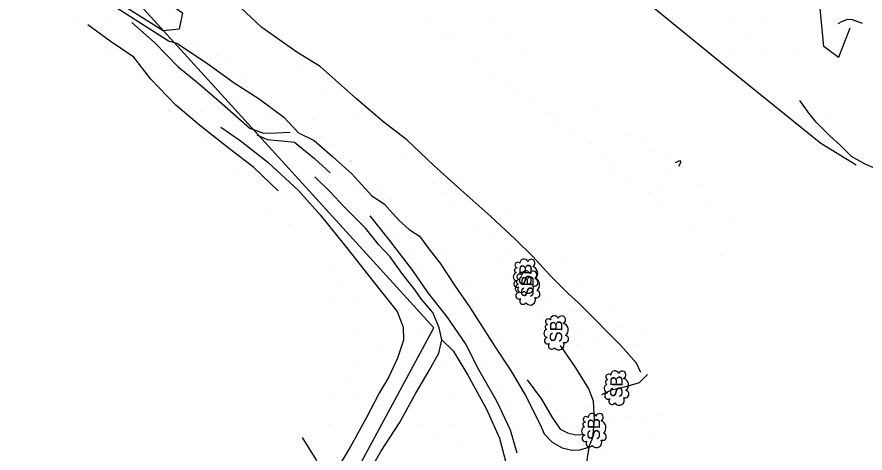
# Model space of a CAD drawing. Extents: x 19528164 to 19545171, y 7585743 to 7602745.
# Drawn here: x 19530420 to 19530964, y 7590962 to 7591242 of the extents above; entities that cross this region are included whole.
import ezdxf

# ---------------------------------------------------------------- set-up
doc = ezdxf.new("R2010")
doc.units = 0
for name, color, linetype in [('Default', 7, 'Continuous'), ('PhoBreakLine', 7, 'Continuous'), ('PhoCulvert', 7, 'Continuous'), ('PhoISAEPoints', 7, 'Continuous'), ('PhoSurveyLimits', 7, 'Continuous'), ('PhoVegetation', 7, 'Continuous'), ('SurNaturalCells', 7, 'Continuous')]:
    doc.layers.add(name, color=color, linetype=linetype)

# ---------------------------------------------------------------- blocks, each defined once
blk = doc.blocks.new('SHRUB')
at = {"layer": 'Default'}
for centre, radius, start, end in [((-5.57, 5.14), 2.08, 10.5948, 214.3611), ((-0.81, 4.83), 2.81, 22.6036, 165.7836), ((3.27, 5.33), 1.59, 0.4605, 158.7839), ((6.61, 4.92), 1.8, 311.3936, 166.4114), ((-8.06, -2.12), 3.34, 125.8289, 299.2848), ((-8.82, 2.41), 2.18, 45.3455, 236.8073), ((8, 0.98), 2.6, 290.9039, 94.3687), ((-4.25, -5.95), 2.36, 157.0258, 349.7602), ((1.54, -3.45), 4.54, 220.0183, 343.6977), ((8.09, -3.71), 2.42, 204.8294, 69.8871)]:
    blk.add_arc(centre, radius, start, end, dxfattribs=at)
blk.add_text('SB', height=7.998, dxfattribs=at).set_placement((-6.62, -4.17))

msp = doc.modelspace()

# ---------------------------------------------------------------- linework, layer by layer
at = {"layer": 'PhoBreakLine'}
for points in [[(19530958.62, 7591146.45), (19530935.96, 7591160.42), (19530877.06, 7591207.86), (19530821.43, 7591253.41), (19530757.71, 7591304.42), (19530691.34, 7591359.14), (19530627.59, 7591412.48), (19530548.14, 7591471.69), (19530520.95, 7591498.59), (19530518.59, 7591512.8), (19530520.19, 7591521.96)], [(19530614.51, 7591209.79), (19530599.48, 7591218.98), (19530577.11, 7591234.92), (19530553.06, 7591257.5), (19530528.71, 7591275.49), (19530499.96, 7591300.16), (19530470.89, 7591323.45), (19530447.93, 7591343.39), (19530419.35, 7591366.44), (19530395.66, 7591387.51), (19530367.82, 7591410.31), (19530342.4, 7591430.71), (19530313.46, 7591452.79), (19530284.41, 7591476.2)], [(19530428.45, 7591286.93), (19530449.8, 7591271.1), (19530480.16, 7591249.8), (19530508.07, 7591232.05), (19530517.08, 7591226.35), (19530522.95, 7591224.48)], [(19530954.64, 7591234.5), (19530947.42, 7591215.59), (19530938.04, 7591222.58), (19530935.37, 7591249.47)], [(19530587.58, 7591130.01), (19530571.82, 7591144.85), (19530556.19, 7591157), (19530537.03, 7591172.18), (19530521.78, 7591184.9), (19530505.73, 7591201.61), (19530494.85, 7591215.79), (19530479.6, 7591225.96), (19530465.37, 7591236.52)], [(19530493.62, 7591238.04), (19530508.36, 7591225.08), (19530523.21, 7591209.53), (19530523.21, 7591209.53), (19530535.7, 7591199.6), (19530549.69, 7591187.59), (19530569.42, 7591170.12), (19530578.12, 7591166.98), (19530586.47, 7591167.23), (19530595.18, 7591167.66)], [(19530962.83, 7591237.33), (19530956.4, 7591239.66), (19530952.87, 7591239.91), (19530949.24, 7591238.43), (19530947.04, 7591237.25)], [(19530522.95, 7591224.48), (19530542.26, 7591211.58), (19530559.32, 7591199.29), (19530575.37, 7591189.01), (19530591.17, 7591177.27), (19530600.49, 7591167.2), (19530610.67, 7591162.19), (19530622.41, 7591152.02), (19530634.73, 7591140.77), (19530647.57, 7591126.78), (19530655.54, 7591121.52), (19530664.78, 7591111.27), (19530671.64, 7591105.1), (19530678.37, 7591100.91), (19530684.18, 7591092.82), (19530691.3, 7591083.67), (19530701.09, 7591068.82), (19530710.45, 7591055.49), (19530718.72, 7591042.45), (19530726.19, 7591030.55), (19530736.78, 7591014.88), (19530746.16, 7590998.94), (19530755.75, 7590979.88), (19530758.45, 7590973.86), (19530763.54, 7590968.49), (19530769.92, 7590965), (19530776.06, 7590963.46), (19530781.29, 7590963.6), (19530786.93, 7590965.34), (19530789.5, 7590971.51), (19530790.6, 7590982.83), (19530790.09, 7590994.9), (19530787.04, 7591002.86), (19530778.78, 7591016.25), (19530768.81, 7591030.75)], [(19530820.43, 7591013.29), (19530817.59, 7591019.23), (19530807.48, 7591030.66), (19530799.16, 7591038.92), (19530790.14, 7591048.17), (19530780.36, 7591058.09), (19530773.66, 7591064), (19530762.34, 7591075.4), (19530751.1, 7591087.77), (19530739.81, 7591099.03), (19530724.17, 7591113.56), (19530704.88, 7591130.56), (19530687.38, 7591146.23), (19530670.04, 7591162.69), (19530654.41, 7591174.66), (19530637.88, 7591188.93), (19530614.51, 7591209.79)], [(19530971.48, 7591144.19), (19530964.47, 7591147.13), (19530955.72, 7591152.08), (19530948.4, 7591159.18), (19530941.84, 7591165.23), (19530932.99, 7591174.06), (19530928.61, 7591179.51), (19530922.57, 7591187.9)], [(19530550.69, 7591170.8), (19530563.11, 7591162.21), (19530580.92, 7591148.29), (19530600.48, 7591130.16), (19530614.58, 7591114.45), (19530632.27, 7591092.51), (19530647.29, 7591073.38), (19530663.97, 7591052.42), (19530667.84, 7591042.43), (19530667.95, 7591034.18), (19530664.24, 7591022.5), (19530658.51, 7591010.63), (19530652.31, 7591000.06), (19530644.25, 7590984.42), (19530633.83, 7590965.38), (19530623.69, 7590948.7)], [(19530573.9, 7591165.94), (19530580.43, 7591162.94), (19530589.74, 7591162.13), (19530598.06, 7591161.31), (19530610.84, 7591150.79), (19530620.87, 7591141.52)], [(19530633.29, 7590927.79), (19530642.08, 7590942.64), (19530653.35, 7590962.66), (19530665.41, 7590981.02), (19530675.99, 7591000.09), (19530684.57, 7591014.52), (19530690.6, 7591025.66), (19530690.6, 7591025.66), (19530692.67, 7591034.39), (19530690.91, 7591042.02), (19530686.94, 7591051.91), (19530679.36, 7591060.62), (19530675.4, 7591066.27), (19530666.86, 7591077.03), (19530659.34, 7591087.61), (19530652.15, 7591095.26), (19530643.55, 7591105.89), (19530630.63, 7591119.04), (19530620.41, 7591129.76), (19530611.11, 7591138.96)], [(19530646.35, 7591113.97), (19530658.88, 7591098.24), (19530673.77, 7591078.77), (19530683.65, 7591064.38), (19530695.77, 7591049.07), (19530708.11, 7591031.35), (19530716, 7591015.74), (19530727.89, 7590994.66), (19530736.46, 7590976.52), (19530740.72, 7590961.82)], [(19530692.67, 7591034.39), (19530699.87, 7591027.21), (19530709.28, 7591011.65), (19530721.4, 7590989.7), (19530729.65, 7590971.15), (19530733.63, 7590955.63), (19530734.22, 7590942.42), (19530735.5, 7590924.2), (19530736.34, 7590906.03), (19530734.16, 7590889.81), (19530731, 7590872.82), (19530727.68, 7590857.77), (19530720.64, 7590841.48), (19530711.53, 7590822.22), (19530701.58, 7590802.09), (19530687.32, 7590778.37), (19530676.57, 7590761.63), (19530665.03, 7590741.43), (19530651.51, 7590719.23), (19530635.74, 7590694.91), (19530622.44, 7590672.51)], [(19530747.41, 7591008.53), (19530756.63, 7590996.23), (19530763.53, 7590984.52), (19530768.52, 7590977.01), (19530773.28, 7590974.53), (19530778.77, 7590973.24), (19530783.75, 7590973.54)], [(19530795.4, 7590999.3), (19530801.65, 7591002.09), (19530811.63, 7591004.45), (19530819.62, 7591006.89), (19530824.61, 7591012.13)], [(19530603.02, 7590971.6), (19530611.71, 7590957.55), (19530621.26, 7590939.63), (19530627.37, 7590926.96), (19530631.44, 7590914.42), (19530633.66, 7590901.52), (19530633.81, 7590888.67), (19530632.93, 7590877.92), (19530628.32, 7590863.06), (19530620.65, 7590847.69), (19530611.64, 7590832.33), (19530603.13, 7590819.45), (19530591.06, 7590802.78)], [(19530786.93, 7590965.34), (19530785.58, 7590955.69), (19530783.89, 7590943.27), (19530783.93, 7590935.51), (19530779.32, 7590925.7)]]:
    msp.add_lwpolyline(points, dxfattribs=at)
at = {"layer": 'PhoCulvert'}
msp.add_lwpolyline([(19530842.62, 7591148.14), (19530845.28, 7591149.4), (19530846.17, 7591148.29), (19530844.61, 7591145.49)], dxfattribs=at)
at = {"layer": 'PhoISAEPoints'}
for p, q in [((19530840.74, 7591241.05), (19530840.74, 7591241.05)), ((19530456.92, 7591239.11), (19530456.92, 7591239.11)), ((19530476.27, 7591237.75), (19530476.27, 7591237.75)), ((19530681.36, 7591238.28), (19530681.36, 7591238.28)), ((19530722.52, 7591240.72), (19530722.52, 7591240.72)), ((19530879.95, 7591238.91), (19530879.95, 7591238.91)), ((19530898.73, 7591238.77), (19530898.73, 7591238.77)), ((19530920, 7591240), (19530920, 7591240)), ((19530525.21, 7591235.19), (19530525.21, 7591235.19)), ((19530529.95, 7591231), (19530529.95, 7591231)), ((19530690.21, 7591235.04), (19530690.21, 7591235.04)), ((19530732.79, 7591230.08), (19530732.79, 7591230.08)), ((19530889.87, 7591230.28), (19530889.87, 7591230.28)), ((19530537.3, 7591225.9), (19530537.3, 7591225.9)), ((19530693.36, 7591229.15), (19530693.36, 7591229.15)), ((19530701.11, 7591227.98), (19530701.11, 7591227.98)), ((19530477.45, 7591219.59), (19530477.45, 7591219.59)), ((19530602.71, 7591220.67), (19530602.71, 7591220.67)), ((19530706, 7591220.64), (19530706, 7591220.64)), ((19530743.37, 7591220.87), (19530743.37, 7591220.87)), ((19530880, 7591220), (19530880, 7591220)), ((19530898.8, 7591219.42), (19530898.8, 7591219.42)), ((19530920, 7591220), (19530920, 7591220)), ((19530523.65, 7591216.32), (19530523.65, 7591216.32)), ((19530548.08, 7591216.77), (19530548.08, 7591216.77)), ((19530714.93, 7591216.14), (19530714.93, 7591216.14)), ((19530961.55, 7591217.62), (19530961.55, 7591217.62)), ((19530556.55, 7591212.58), (19530556.55, 7591212.58)), ((19530602.52, 7591208.77), (19530602.52, 7591208.77)), ((19530756.15, 7591209.18), (19530756.15, 7591209.18)), ((19530543.12, 7591203.21), (19530543.12, 7591203.21)), ((19530563.41, 7591204.29), (19530563.41, 7591204.29)), ((19530725.73, 7591205.11), (19530725.73, 7591205.11)), ((19530498.74, 7591201.73), (19530498.74, 7591201.73)), ((19530522.95, 7591199.95), (19530522.95, 7591199.95)), ((19530572.41, 7591199.03), (19530572.41, 7591199.03)), ((19530736.6, 7591199.4), (19530736.6, 7591199.4)), ((19530769.38, 7591200.15), (19530769.38, 7591200.15)), ((19530898.04, 7591198.03), (19530898.04, 7591198.03)), ((19530919.85, 7591198.72), (19530919.85, 7591198.72)), ((19530940.4, 7591198.09), (19530940.4, 7591198.09)), ((19530961.01, 7591198.09), (19530961.01, 7591198.09)), ((19530618.18, 7591195.11), (19530618.18, 7591195.11)), ((19530783.28, 7591192.02), (19530783.28, 7591192.02)), ((19530562.69, 7591189.61), (19530562.69, 7591189.61)), ((19530583.07, 7591189.62), (19530583.07, 7591189.62)), ((19530739.47, 7591191.66), (19530739.47, 7591191.66)), ((19530749.82, 7591189.8), (19530749.82, 7591189.8)), ((19530591.83, 7591184.44), (19530591.83, 7591184.44)), ((19530792.58, 7591182.05), (19530792.58, 7591182.05)), ((19530517.58, 7591180.88), (19530517.58, 7591180.88)), ((19530537.72, 7591180.82), (19530537.72, 7591180.82)), ((19530580.65, 7591176.97), (19530580.65, 7591176.97)), ((19530638.19, 7591178.17), (19530638.19, 7591178.17)), ((19530759.18, 7591180.11), (19530759.18, 7591180.11)), ((19530766.86, 7591179.06), (19530766.86, 7591179.06)), ((19530919.16, 7591178.51), (19530919.16, 7591178.51)), ((19530939.48, 7591179.25), (19530939.48, 7591179.25)), ((19530959.62, 7591177.82), (19530959.62, 7591177.82)), ((19530768.3, 7591172.52), (19530768.3, 7591172.52)), ((19530806.57, 7591172.51), (19530806.57, 7591172.51)), ((19530608.64, 7591170.12), (19530608.64, 7591170.12)), ((19530614.99, 7591165), (19530614.99, 7591165)), ((19530653.4, 7591166.2), (19530653.4, 7591166.2)), ((19530778.21, 7591166.66), (19530778.21, 7591166.66)), ((19530813.4, 7591165.29), (19530813.4, 7591165.29)), ((19530539.16, 7591160.94), (19530539.16, 7591160.94)), ((19530621.43, 7591159.65), (19530621.43, 7591159.65)), ((19530788.45, 7591160.23), (19530788.45, 7591160.23)), ((19530821.31, 7591161.92), (19530821.31, 7591161.92)), ((19530938.71, 7591163.31), (19530938.71, 7591163.31)), ((19530829.17, 7591155.11), (19530829.17, 7591155.11)), ((19530593.73, 7591148.52), (19530593.73, 7591148.52)), ((19530617.95, 7591151.86), (19530617.95, 7591151.86)), ((19530629.62, 7591152.83), (19530629.62, 7591152.83)), ((19530634, 7591148.97), (19530634, 7591148.97)), ((19530669.54, 7591152.57), (19530669.54, 7591152.57)), ((19530795.96, 7591152.05), (19530795.96, 7591152.05)), ((19530804.46, 7591148.92), (19530804.46, 7591148.92)), ((19530835.39, 7591153.47), (19530835.39, 7591153.47)), ((19530637.82, 7591143.68), (19530637.82, 7591143.68)), ((19530678.31, 7591145.65), (19530678.31, 7591145.65)), ((19530838.28, 7591147.53), (19530838.28, 7591147.53)), ((19530560, 7591140), (19530560, 7591140)), ((19530627.87, 7591141.29), (19530627.87, 7591141.29)), ((19530644.46, 7591137.62), (19530644.46, 7591137.62)), ((19530702.89, 7591138.11), (19530702.89, 7591138.11)), ((19530804.15, 7591140.82), (19530804.15, 7591140.82)), ((19530812.09, 7591137.87), (19530812.09, 7591137.87)), ((19530837.18, 7591140.81), (19530837.18, 7591140.81)), ((19530848.68, 7591140.26), (19530848.68, 7591140.26)), ((19530608.48, 7591134.8), (19530608.48, 7591134.8)), ((19530635.02, 7591133.36), (19530635.02, 7591133.36)), ((19530650.64, 7591132.49), (19530650.64, 7591132.49)), ((19530686.64, 7591134.79), (19530686.64, 7591134.79)), ((19530833.85, 7591133.55), (19530833.85, 7591133.55)), ((19530857.3, 7591134.08), (19530857.3, 7591134.08)), ((19530642.11, 7591128.59), (19530642.11, 7591128.59)), ((19530692.82, 7591129.08), (19530692.82, 7591129.08)), ((19530825.29, 7591128.81), (19530825.29, 7591128.81)), ((19530660.08, 7591124.65), (19530660.08, 7591124.65)), ((19530833.44, 7591122.44), (19530833.44, 7591122.44)), ((19530865.88, 7591122.97), (19530865.88, 7591122.97)), ((19530865.88, 7591122.97), (19530865.88, 7591122.97)), ((19530582.04, 7591118.13), (19530582.04, 7591118.13)), ((19530648.67, 7591116.18), (19530648.67, 7591116.18)), ((19530700.14, 7591121.08), (19530700.14, 7591121.08)), ((19530708.99, 7591115.84), (19530708.99, 7591115.84)), ((19530842.84, 7591116), (19530842.84, 7591116)), ((19530627.23, 7591113.58), (19530627.23, 7591113.58)), ((19530673.12, 7591113), (19530673.12, 7591113)), ((19530732.8, 7591114.67), (19530732.8, 7591114.67)), ((19530594.07, 7591108.41), (19530594.07, 7591108.41)), ((19530656.5, 7591107.15), (19530656.5, 7591107.15)), ((19530678.67, 7591105.59), (19530678.67, 7591105.59)), ((19530713.78, 7591106.96), (19530713.78, 7591106.96)), ((19530852.37, 7591106.38), (19530852.37, 7591106.38)), ((19530878.01, 7591109.7), (19530878.01, 7591109.7)), ((19530665.65, 7591101.79), (19530665.65, 7591101.79)), ((19530685.58, 7591099.43), (19530685.58, 7591099.43)), ((19530723.52, 7591100.12), (19530723.52, 7591100.12)), ((19530860.1, 7591100.33), (19530860.1, 7591100.33)), ((19530607.28, 7591094.39), (19530607.28, 7591094.39)), ((19530672.84, 7591093.1), (19530672.84, 7591093.1)), ((19530691.8, 7591090.83), (19530691.8, 7591090.83)), ((19530735.12, 7591091.83), (19530735.12, 7591091.83)), ((19530757.4, 7591090.27), (19530757.4, 7591090.27)), ((19530728.26, 7591086.36), (19530728.26, 7591086.36)), ((19530770.1, 7591084.55), (19530770.1, 7591084.55)), ((19530871.35, 7591088.24), (19530871.35, 7591088.24)), ((19530600, 7591080), (19530600, 7591080)), ((19530620, 7591080), (19530620, 7591080)), ((19530679.6, 7591080.76), (19530679.6, 7591080.76)), ((19530700.34, 7591078.63), (19530700.34, 7591078.63)), ((19530740.6, 7591080.79), (19530740.6, 7591080.79)), ((19530736.27, 7591075.76), (19530736.27, 7591075.76)), ((19530754.1, 7591073.64), (19530754.1, 7591073.64)), ((19530629.25, 7591068.75), (19530629.25, 7591068.75)), ((19530706.86, 7591069.33), (19530706.86, 7591069.33)), ((19530783.09, 7591071.02), (19530783.09, 7591071.02)), ((19530693.56, 7591066.39), (19530693.56, 7591066.39)), ((19530749.07, 7591066.19), (19530749.07, 7591066.19)), ((19530754.19, 7591065.01), (19530754.19, 7591065.01)), ((19530620, 7591060), (19530620, 7591060)), ((19530640, 7591060), (19530640, 7591060)), ((19530715.24, 7591060.8), (19530715.24, 7591060.8)), ((19530761.93, 7591060.07), (19530761.93, 7591060.07)), ((19530792.26, 7591059.84), (19530792.26, 7591059.84)), ((19530801.65, 7591055.97), (19530801.65, 7591055.97)), ((19530801.65, 7591055.97), (19530801.65, 7591055.97)), ((19530753.66, 7591053.21), (19530753.66, 7591053.21)), ((19530766.37, 7591054.79), (19530766.37, 7591054.79)), ((19530774.54, 7591052.56), (19530774.54, 7591052.56)), ((19530756.62, 7591047.94), (19530756.62, 7591047.94)), ((19530764.19, 7591047.16), (19530764.19, 7591047.16)), ((19530797.38, 7591049.32), (19530797.38, 7591049.32)), ((19530640, 7591040), (19530640, 7591040)), ((19530680, 7591040), (19530680, 7591040)), ((19530726.42, 7591043.85), (19530726.42, 7591043.85)), ((19530782.22, 7591041.12), (19530782.22, 7591041.12)), ((19530808.25, 7591042.33), (19530808.25, 7591042.33)), ((19530820, 7591040), (19530820, 7591040)), ((19530711.52, 7591036.98), (19530711.52, 7591036.98)), ((19530731.98, 7591034.54), (19530731.98, 7591034.54)), ((19530792.68, 7591034.63), (19530792.68, 7591034.63)), ((19530625.84, 7591032.82), (19530625.84, 7591032.82)), ((19530652.97, 7591031.23), (19530652.97, 7591031.23)), ((19530779.15, 7591031.32), (19530779.15, 7591031.32)), ((19530818.26, 7591031.26), (19530818.26, 7591031.26)), ((19530832.81, 7591023.94), (19530832.81, 7591023.94)), ((19530640, 7591020), (19530640, 7591020)), ((19530720, 7591020), (19530720, 7591020)), ((19530801.29, 7591022.26), (19530801.29, 7591022.26)), ((19530672.02, 7591015.78), (19530672.02, 7591015.78)), ((19530696.45, 7591017.14), (19530696.45, 7591017.14)), ((19530786.93, 7591015.8), (19530786.93, 7591015.8)), ((19530793.18, 7591013.74), (19530793.18, 7591013.74)), ((19530630.71, 7591009.3), (19530630.71, 7591009.3)), ((19530839.5, 7591009.1), (19530839.5, 7591009.1)), ((19530728.16, 7591004.54), (19530728.16, 7591004.54)), ((19530760.11, 7591001.8), (19530760.11, 7591001.8)), ((19530620, 7591000), (19530620, 7591000)), ((19530640, 7591000), (19530640, 7591000)), ((19530659.76, 7590996.63), (19530659.76, 7590996.63)), ((19530700, 7591000), (19530700, 7591000)), ((19530829.42, 7590996.4), (19530829.42, 7590996.4)), ((19530688.82, 7590992.55), (19530688.82, 7590992.55)), ((19530709.69, 7590991.51), (19530709.69, 7590991.51)), ((19530736.13, 7590991.61), (19530736.13, 7590991.61)), ((19530784.91, 7590990.75), (19530784.91, 7590990.75)), ((19530765.99, 7590988.75), (19530765.99, 7590988.75)), ((19530813.75, 7590985.09), (19530813.75, 7590985.09)), ((19530834.5, 7590985.91), (19530834.5, 7590985.91)), ((19530620, 7590980), (19530620, 7590980)), ((19530680, 7590980), (19530680, 7590980)), ((19530700, 7590980), (19530700, 7590980)), ((19530740, 7590980), (19530740, 7590980)), ((19530770.83, 7590983.76), (19530770.83, 7590983.76)), ((19530803.02, 7590983.22), (19530803.02, 7590983.22)), ((19530822.47, 7590980.32), (19530822.47, 7590980.32)), ((19530715.92, 7590977.89), (19530715.92, 7590977.89)), ((19530750.26, 7590975.83), (19530750.26, 7590975.83)), ((19530764.3, 7590975.46), (19530764.3, 7590975.46)), ((19530775.43, 7590979.27), (19530775.43, 7590979.27)), ((19530689.82, 7590971.11), (19530689.82, 7590971.11)), ((19530779.62, 7590969.76), (19530779.62, 7590969.76)), ((19530808.96, 7590968.87), (19530808.96, 7590968.87)), ((19530828.35, 7590971.71), (19530828.35, 7590971.71)), ((19530705.41, 7590967.52), (19530705.41, 7590967.52)), ((19530794.58, 7590962.46), (19530794.58, 7590962.46))]:
    msp.add_line(p, q, dxfattribs=at)
at = {"layer": 'PhoSurveyLimits'}
msp.add_lwpolyline([(19530813.08, 7588141.83), (19530826.36, 7590306.58), (19530836.02, 7590358.63), (19530806.78, 7590373.28), (19530757.47, 7590370.26), (19530695.18, 7590346.98), (19530641.2, 7590285.01), (19530612.99, 7590219.54), (19530561.32, 7590123.06), (19530451.92, 7590109.87), (19530349.02, 7590108.43), (19530203.76, 7589978.43), (19530164.76, 7590012.57), (19530344.64, 7590385.93), (19530300.57, 7590416.51), (19530480.77, 7590658.88), (19530687.59, 7591041.97), (19530295.19, 7591473.06), (19529551.78, 7591996.95)], dxfattribs=at)
at = {"layer": 'PhoVegetation'}
msp.add_lwpolyline([(19530479.64, 7591280.21), (19530485, 7591273.05), (19530526.05, 7591244.24), (19530523.84, 7591233.75), (19530513.7, 7591232.72), (19530474.55, 7591257.45), (19530428.06, 7591291.95), (19530434.83, 7591296.96), (19530442.28, 7591297.66), (19530448.85, 7591290.33), (19530452.71, 7591288.29), (19530461.35, 7591285.04), (19530469.98, 7591283.48), (19530476.35, 7591282.99)], close=True, dxfattribs=at)
at = {"layer": 'SurNaturalCells'}
msp.add_line((19530609.27, 7591175.77), (19530609.27, 7591175.79), dxfattribs=at)
msp.add_line((19530609.27, 7591175.77), (19530609.27, 7591175.79), dxfattribs=at)
msp.add_circle((19530609.27, 7591175.78), 0.00459, dxfattribs=at)

# ---------------------------------------------------------------- block references
at = {"layer": 'PhoVegetation', "xscale": 0.9999999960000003, "yscale": 0.9999999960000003, "rotation": 88.89301078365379}
for p in [(19530746.18, 7591075.56), (19530747.42, 7591068.04), (19530765.81, 7591039.18), (19530804.54, 7591003.75), (19530790.03, 7590976.49)]:
    msp.add_blockref('SHRUB', p, dxfattribs=at)

doc.saveas('drawing.dxf')
